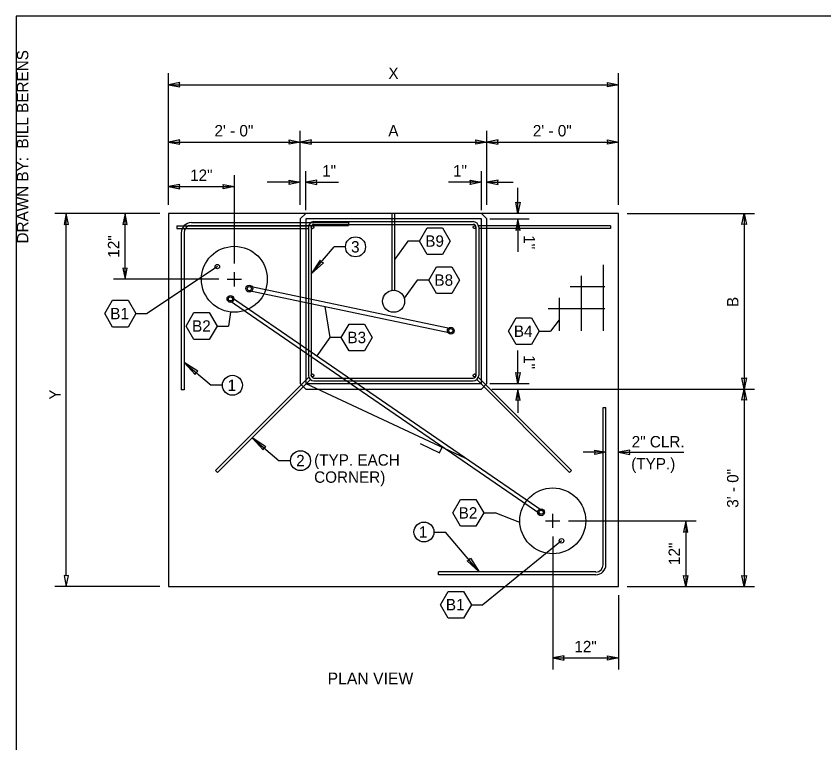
# Model space of a CAD drawing. Extents: x 99862 to 103151, y 100000 to 117076.
# Drawn here: x 99862 to 100994, y 107057 to 108076 of the extents above; entities that cross this region are included whole.
import ezdxf

# ---------------------------------------------------------------- set-up
doc = ezdxf.new("R2010")
doc.units = 0
for name, color, linetype in [('Default', 7, 'Continuous'), ('Level 1', 7, 'Continuous'), ('Level 11', 7, 'Continuous'), ('Level 14', 7, 'Continuous'), ('Level 15', 7, 'Continuous'), ('Level 20', 7, 'Continuous'), ('Level 62', 7, 'Continuous'), ('Level 9', 7, 'Continuous')]:
    doc.layers.add(name, color=color, linetype=linetype)

msp = doc.modelspace()

# ---------------------------------------------------------------- linework, layer by layer
at = {"layer": 'Default'}
for p, q in [((100087.1, 107781.6), (100272.1, 107781.6)), ((100087.1, 107781.6), (100087.1, 107777.8)), ((100107.6, 107786.1), (100327.9, 107786.1)), ((100107.6, 107782.2), (100327.9, 107782.2)), ((100276.2, 107781.6), (100277.6, 107781.6)), ((100279.5, 107787.4), (100502.7, 107787.4)), ((100279.5, 107783.6), (100502.7, 107783.6)), ((100327.9, 107786.1), (100327.9, 107782.2)), ((100506, 107781.6), (100504.6, 107781.6)), ((100695, 107781.6), (100510.1, 107781.6)), ((100695, 107781.6), (100695, 107777.8)), ((100087.1, 107777.8), (100271.8, 107777.8)), ((100093.5, 107771.9), (100093.5, 107551.6)), ((100097.3, 107771.9), (100097.3, 107551.6)), ((100271.8, 107779.7), (100271.8, 107571.9)), ((100275.7, 107779.7), (100275.7, 107571.9)), ((100275.7, 107777.8), (100277.6, 107777.8)), ((100506.5, 107777.8), (100504.6, 107777.8)), ((100506.5, 107779.7), (100506.5, 107571.9)), ((100510.4, 107779.7), (100510.4, 107571.9)), ((100695, 107777.8), (100510.4, 107777.8)), ((100141.6, 107438.6), (100272.3, 107569.3)), ((100144.3, 107435.9), (100274.5, 107566.1)), ((100275.7, 107572.7), (100276.2, 107573.3)), ((100277.2, 107568.9), (100278.9, 107570.6)), ((100279.5, 107568.1), (100502.7, 107568.1)), ((100505, 107568.9), (100503.2, 107570.6)), ((100506.5, 107572.7), (100506, 107573.3)), ((100637.9, 107435.9), (100507.7, 107566.1)), ((100640.6, 107438.6), (100509.9, 107569.3)), ((100279.5, 107564.3), (100502.7, 107564.3)), ((100097.3, 107551.6), (100093.5, 107551.6)), ((100684.9, 107306.5), (100684.9, 107526.9)), ((100684.9, 107526.9), (100688.7, 107526.9)), ((100688.7, 107306.5), (100688.7, 107526.9)), ((100141.6, 107438.6), (100144.3, 107435.9)), ((100640.6, 107438.6), (100637.9, 107435.9)), ((100674.6, 107296.3), (100454.2, 107296.3)), ((100454.2, 107292.4), (100454.2, 107296.3)), ((100674.6, 107292.4), (100454.2, 107292.4))]:
    msp.add_line(p, q, dxfattribs=at)
for centre in [(100277.6, 107779.7), (100504.6, 107779.7), (100277.6, 107571.9), (100504.6, 107571.9)]:
    msp.add_circle(centre, 1.92, dxfattribs=at)
for centre, radius, start, end in [((100107.6, 107771.9), 14.1, 90, 180), ((100107.6, 107771.9), 10.3, 90, 180), ((100279.5, 107779.7), 7.7, 90, 180), ((100279.5, 107779.7), 3.85, 90, 180), ((100502.7, 107779.7), 7.7, 0, 90), ((100502.7, 107779.7), 3.85, 0, 90), ((100279.5, 107571.9), 7.7, 180, 270), ((100279.5, 107571.9), 3.85, 180, 270), ((100502.7, 107571.9), 7.7, 270, 0), ((100502.7, 107571.9), 3.85, 270, 360), ((100674.6, 107306.5), 10.3, 270, 0), ((100674.6, 107306.5), 14.1, 270, 0)]:
    msp.add_arc(centre, radius, start, end, dxfattribs=at)
at = {"layer": 'Level 1'}
for p, q in [((100684.8, 107726.9), (100684.8, 107696.1)), ((100654, 107711.5), (100654, 107696.1)), ((100188.2, 107690.7), (100470.7, 107631.6)), ((100471.9, 107637.3), (100189.4, 107696.3)), ((100654, 107696.1), (100638.6, 107696.1)), ((100684.8, 107696.1), (100654, 107696.1)), ((100654, 107696.1), (100654, 107665.3)), ((100684.8, 107696.1), (100684.8, 107665.3)), ((100687.3, 107696.1), (100684.8, 107696.1)), ((100164, 107681.5), (100599.5, 107382.4)), ((100623.2, 107680.7), (100623.2, 107665.3)), ((100596.2, 107377.6), (100160.8, 107676.7)), ((100623.2, 107665.3), (100607.8, 107665.3)), ((100654, 107665.3), (100623.2, 107665.3)), ((100623.2, 107665.3), (100623.2, 107634.5)), ((100684.8, 107665.3), (100654, 107665.3)), ((100654, 107665.3), (100654, 107634.5)), ((100684.8, 107665.3), (100684.8, 107634.5)), ((100687.3, 107665.3), (100684.8, 107665.3))]:
    msp.add_line(p, q, dxfattribs=at)
msp.add_lwpolyline([(99862, 105999.5), (103151, 105999.5), (103151, 108075.5), (99862, 108075.5)], close=True, dxfattribs=at)
for centre, radius in [((100144.1, 107724.4), 3.13), ((100188.8, 107693.5), 4.81), ((100188.8, 107693.5), 2.89), ((100162.4, 107679.1), 4.81), ((100162.4, 107679.1), 2.89), ((100471.3, 107634.5), 4.81), ((100471.3, 107634.5), 2.89), ((100597.9, 107380), 4.81), ((100597.9, 107380), 2.89), ((100626.5, 107339.9), 3.13)]:
    msp.add_circle(centre, radius, dxfattribs=at)
at = {"layer": 'Level 11'}
for points in [[(100706.6, 107798.9), (100075.6, 107798.9), (100075.6, 107275.7), (100706.6, 107275.7)], [(100268, 107552.7), (100514.2, 107552.7), (100521.9, 107560.4), (100521.9, 107791.3), (100514.2, 107798.9), (100268, 107798.9), (100260.3, 107791.3), (100260.3, 107560.4)]]:
    msp.add_lwpolyline(points, close=True, dxfattribs=at)
for centre, radius in [((100167.9, 107706.6), 46.2), ((100391.1, 107675.8), 15.4), ((100614.2, 107368), 46.2)]:
    msp.add_circle(centre, radius, dxfattribs=at)
at = {"layer": 'Level 14'}
for points in [[(100389.2, 107691.1), (100389.2, 107798.9)], [(100393, 107691.1), (100393, 107798.9)]]:
    msp.add_lwpolyline(points, dxfattribs=at)
at = {"layer": 'Level 15'}
for p, q in [((100075.6, 107810.9), (100075.6, 107995.4)), ((100706.6, 107810.9), (100706.6, 107995.4)), ((100075.6, 107979.4), (100706.6, 107979.4)), ((100260.3, 107810.9), (100260.3, 107914.9)), ((100521.9, 107810.9), (100521.9, 107914.9)), ((100075.6, 107898.9), (100260.3, 107898.9)), ((100260.3, 107898.9), (100521.9, 107898.9)), ((100521.9, 107898.9), (100706.6, 107898.9)), ((100167.9, 107728.6), (100167.9, 107852.5)), ((100268, 107803.3), (100268, 107858.2)), ((100514.2, 107803.3), (100514.2, 107858.2)), ((100075.6, 107836.5), (100167.9, 107836.5)), ((100260.3, 107842.6), (100214.1, 107842.6)), ((100268, 107842.6), (100314.1, 107842.6)), ((100514.2, 107842.6), (100468, 107842.6)), ((100521.9, 107842.6), (100558.7, 107842.6)), ((100565.5, 107798.9), (100565.5, 107834.7)), ((100063.6, 107798.9), (99916.3, 107798.9)), ((99932.3, 107291.1), (99932.3, 107798.9)), ((100014.6, 107706.6), (100014.6, 107798.9)), ((100526.2, 107791.3), (100581.1, 107791.3)), ((100565.5, 107791.3), (100565.5, 107745.1)), ((100718.6, 107798.9), (100897, 107798.9)), ((100882.5, 107798.9), (100882.5, 107552.7)), ((100411.3, 107760.2), (100393, 107734.6)), ((100427.3, 107760.2), (100411.3, 107760.2)), ((100275.7, 107714.2), (100307.7, 107752.1)), ((100323.7, 107752.1), (100307.7, 107752.1)), ((100144.1, 107724.4), (100045.7, 107658.5)), ((100167.9, 107696.6), (100167.9, 107716.6)), ((100145.9, 107706.6), (99998.6, 107706.6)), ((100157.9, 107706.6), (100177.9, 107706.6)), ((100424.3, 107705.5), (100405.9, 107679.9)), ((100440.3, 107705.5), (100424.3, 107705.5)), ((100294.5, 107668.5), (100301.8, 107625)), ((100029.7, 107658.5), (100045.7, 107658.5)), ((100162.6, 107660.7), (100159.6, 107641.1)), ((100623.2, 107649.9), (100611.3, 107633.8)), ((100143.6, 107641.1), (100159.6, 107641.1)), ((100595.3, 107633.8), (100611.3, 107633.8)), ((100301.8, 107625), (100283.5, 107599.4)), ((100317.8, 107625), (100301.8, 107625)), ((100565.5, 107560.4), (100565.5, 107606.6)), ((100097.3, 107590.1), (100135.2, 107558)), ((100151.2, 107558), (100135.2, 107558)), ((100526.2, 107560.4), (100581.1, 107560.4)), ((100529, 107552.7), (100897, 107552.7)), ((100565.5, 107552.7), (100565.5, 107519.2)), ((100882.5, 107552.7), (100882.5, 107275.7)), ((100192.8, 107484.4), (100230.7, 107452.3)), ((100688.7, 107464), (100656.7, 107464)), ((100706.6, 107464), (100798.2, 107464)), ((100246.6, 107452.3), (100230.6, 107452.3)), ((100517.4, 107379.1), (100533.4, 107379.1)), ((100568.1, 107365.5), (100533.4, 107379.1)), ((100614.2, 107358), (100614.2, 107378)), ((100604.2, 107368), (100624.2, 107368)), ((100636.2, 107368), (100815.1, 107368)), ((100800.6, 107368), (100800.6, 107275.7)), ((100447.7, 107352.3), (100463.7, 107352.3)), ((100511.1, 107296.3), (100463.8, 107352.2)), ((100626.5, 107339.9), (100516.1, 107250.4)), ((100614.2, 107346), (100614.2, 107159.7)), ((100063.6, 107275.7), (99916.3, 107275.7)), ((100718.6, 107275.7), (100897, 107275.7)), ((100706.6, 107263.7), (100706.6, 107159.7)), ((100500.1, 107250.4), (100516.1, 107250.4)), ((100614.2, 107175.7), (100706.6, 107175.7))]:
    msp.add_line(p, q, dxfattribs=at)
for points in [[(100075.6, 107979.4), (100091.3, 107976.3), (100090.6, 107979.4), (100091.3, 107982.5)], [(100706.6, 107979.4), (100690.9, 107976.3), (100691.6, 107979.4), (100690.9, 107982.5)], [(100075.6, 107898.9), (100091.3, 107895.9), (100090.6, 107898.9), (100091.3, 107902)], [(100260.3, 107898.9), (100244.5, 107895.9), (100245.3, 107898.9), (100244.5, 107902)], [(100260.3, 107898.9), (100276, 107895.9), (100275.3, 107898.9), (100276, 107902)], [(100521.9, 107898.9), (100506.2, 107895.9), (100506.9, 107898.9), (100506.2, 107902)], [(100521.9, 107898.9), (100537.6, 107895.9), (100536.9, 107898.9), (100537.6, 107902)], [(100706.6, 107898.9), (100690.9, 107895.9), (100691.6, 107898.9), (100690.9, 107902)], [(100075.6, 107836.5), (100091.3, 107833.4), (100090.6, 107836.5), (100091.3, 107839.6)], [(100167.9, 107836.5), (100152.2, 107833.4), (100152.9, 107836.5), (100152.2, 107839.6)], [(100260.3, 107842.6), (100244.5, 107839.5), (100245.3, 107842.6), (100244.5, 107845.6)], [(100268, 107842.6), (100283.7, 107839.5), (100283, 107842.6), (100283.7, 107845.6)], [(100514.2, 107842.6), (100498.5, 107839.5), (100499.2, 107842.6), (100498.5, 107845.6)], [(100521.9, 107842.6), (100537.6, 107839.5), (100536.9, 107842.6), (100537.6, 107845.6)], [(100565.5, 107798.9), (100562.4, 107814.7), (100565.5, 107813.9), (100568.6, 107814.7)], [(99932.3, 107798.9), (99929.2, 107783.2), (99932.3, 107784), (99935.4, 107783.2)], [(100014.6, 107798.9), (100011.5, 107783.2), (100014.6, 107784), (100017.7, 107783.2)], [(100565.5, 107791.3), (100562.4, 107775.5), (100565.5, 107776.3), (100568.6, 107775.5)], [(100882.5, 107798.9), (100885.6, 107783.2), (100882.5, 107784), (100879.5, 107783.2)], [(100275.7, 107714.2), (100292.7, 107729.7), (100289.7, 107730.8), (100288.1, 107733.6)], [(100014.6, 107706.6), (100017.7, 107722.3), (100014.6, 107721.6), (100011.5, 107722.3)], [(100097.3, 107590.1), (100112.8, 107573.1), (100113.9, 107576), (100116.7, 107577.6)], [(100565.5, 107560.4), (100562.4, 107576.1), (100565.5, 107575.4), (100568.6, 107576.1)], [(100882.5, 107552.7), (100879.5, 107568.4), (100882.5, 107567.7), (100885.6, 107568.4)], [(100565.5, 107552.7), (100562.4, 107537), (100565.5, 107537.7), (100568.6, 107537)], [(100882.5, 107552.7), (100885.6, 107537), (100882.5, 107537.7), (100879.5, 107537)], [(100192.8, 107484.4), (100208.3, 107467.4), (100209.4, 107470.3), (100212.1, 107471.9)], [(100688.7, 107464), (100673, 107460.9), (100673.7, 107464), (100673, 107467.1)], [(100706.6, 107464), (100722.3, 107460.9), (100721.6, 107464), (100722.3, 107467.1)], [(100800.6, 107368), (100797.5, 107352.3), (100800.6, 107353), (100803.7, 107352.3)], [(100511.1, 107296.3), (100494.1, 107311.8), (100497.1, 107312.9), (100498.7, 107315.6)], [(99932.3, 107275.7), (99935.4, 107291.4), (99932.3, 107290.7), (99929.2, 107291.4)], [(100800.6, 107275.7), (100797.5, 107291.4), (100800.6, 107290.7), (100803.7, 107291.4)], [(100882.5, 107275.7), (100879.5, 107291.4), (100882.5, 107290.7), (100885.6, 107291.4)], [(100614.2, 107175.7), (100630, 107172.6), (100629.2, 107175.7), (100630, 107178.8)], [(100706.6, 107175.7), (100690.9, 107172.6), (100691.6, 107175.7), (100690.9, 107178.8)]]:
    msp.add_lwpolyline(points, close=True, dxfattribs=at)
at = {"layer": 'Level 20'}
for points in [[(100427.3, 107760.2), (100438.2, 107778.9), (100459.8, 107778.9), (100470.6, 107760.2), (100459.8, 107741.4), (100438.2, 107741.4), (100427.3, 107760.2)], [(100440.3, 107705.5), (100451.1, 107724.2), (100472.7, 107724.2), (100483.5, 107705.5), (100472.7, 107686.7), (100451.1, 107686.7), (100440.3, 107705.5)], [(99986.4, 107658.5), (99997.2, 107677.2), (100018.9, 107677.2), (100029.7, 107658.5), (100018.9, 107639.7), (99997.2, 107639.7), (99986.4, 107658.5)], [(100100.3, 107641.1), (100111.1, 107659.9), (100132.8, 107659.9), (100143.6, 107641.1), (100132.8, 107622.4), (100111.1, 107622.4), (100100.3, 107641.1)], [(100552, 107633.8), (100562.9, 107652.5), (100584.5, 107652.5), (100595.3, 107633.8), (100584.5, 107615), (100562.9, 107615), (100552, 107633.8)], [(100317.8, 107625), (100328.7, 107643.7), (100350.3, 107643.7), (100361.1, 107625), (100350.3, 107606.3), (100328.7, 107606.3), (100317.8, 107625)], [(100474.1, 107379.1), (100484.9, 107397.8), (100506.6, 107397.8), (100517.4, 107379.1), (100506.6, 107360.3), (100484.9, 107360.3), (100474.1, 107379.1)], [(100456.9, 107250.4), (100467.7, 107269.1), (100489.3, 107269.1), (100500.1, 107250.4), (100489.3, 107231.6), (100467.7, 107231.6), (100456.9, 107250.4)]]:
    msp.add_lwpolyline(points, dxfattribs=at)
for centre in [(100337.7, 107752.1), (100165.2, 107558), (100260.6, 107452.3), (100433.7, 107352.3)]:
    msp.add_circle(centre, 14, dxfattribs=at)
at = {"layer": 'Level 9'}
for p, q in [((100268, 107560.4), (100491.1, 107456.3)), ((100428.4, 107476.2), (100455.5, 107463.5)), ((100455.5, 107463.5), (100459.1, 107471.3))]:
    msp.add_line(p, q, dxfattribs=at)
msp.add_lwpolyline([(100268, 107560.4), (100514.2, 107560.4), (100514.2, 107791.3), (100268, 107791.3)], close=True, dxfattribs=at)

# ---------------------------------------------------------------- texts
at = {"layer": 'Level 20'}
for s, height, p in [('X', 16, (100383.8, 107987.4)), ('2\' - 0"', 16, (100140, 107906.9)), ('A', 16, (100383.7, 107906.9)), ('2\' - 0"', 16, (100586.3, 107906.9)), ('12"', 16, (100105.9, 107844.5)), ('1"', 16, (100291, 107850.6)), ('1"', 16, (100474.4, 107850.6)), ('B9', 16, (100435.5, 107752.2)), ('3', 16, (100331.5, 107744.1)), ('B8', 16, (100448.4, 107697.5)), ('B1', 16, (99993.9, 107650.5)), ('B2', 16, (100108.6, 107633.1)), ('B3', 16, (100326.4, 107617)), ('B4', 16, (100559.7, 107625.8)), ('1', 16, (100158.5, 107550)), ('2" CLR.', 16, (100724.9, 107470.9)), ('2', 16, (100254.5, 107444.4)), ('(TYP. EACH', 16, (100279.7, 107445.3)), ('(TYP.)', 16, (100724.2, 107440)), ('CORNER)', 16, (100279.7, 107421.3)), ('B2', 16, (100482.3, 107371.1)), ('1', 16, (100426.6, 107344.3)), ('B1', 16, (100464.4, 107242.4)), ('12"', 16, (100644.5, 107183.7)), ('PLAN VIEW', 16.5, (100298.6, 107138.8))]:
    msp.add_text(s, height=height, dxfattribs=at).set_placement(p)
for s, rotation, p in [('12"', 90, (100006.6, 107736.9)), ('1"', 270, (100573.5, 107768.3)), ('B', 90, (100874.5, 107667.7)), ('1"', 270, (100573.5, 107600.2)), ('Y', 90, (99924.3, 107537.8)), ('3\' - 0"', 90, (100874.5, 107386.3)), ('12"', 90, (100792.6, 107306))]:
    msp.add_text(s, height=16, rotation=rotation, dxfattribs=at).set_placement(p)
at = {"layer": 'Level 62'}
msp.add_text('DRAWN BY:  BILL BERENS', height=16, rotation=90, dxfattribs=at).set_placement((99879, 107756.8))

doc.saveas('drawing.dxf')
